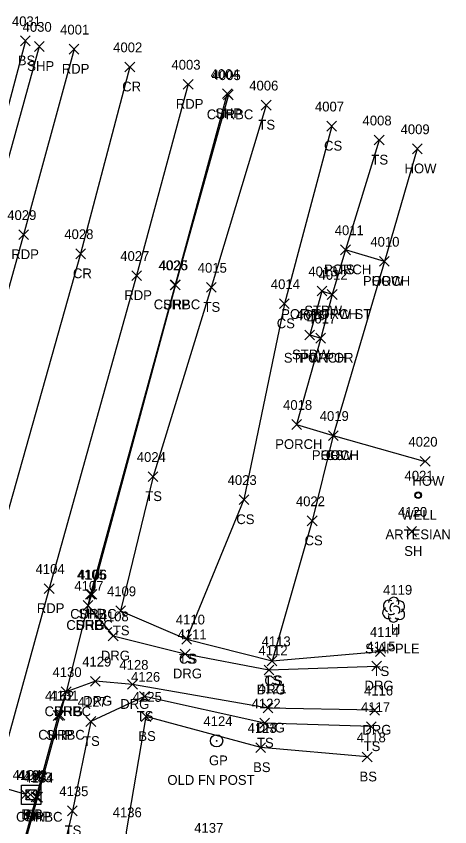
# Model space of a CAD drawing. Extents: x 1443912 to 1445411, y 621446 to 623693.
# Drawn here: x 1445024.9 to 1445113.5, y 623518.7 to 623684.4 of the extents above; entities that cross this region are included whole.
import ezdxf

# ---------------------------------------------------------------- set-up
doc = ezdxf.new("R2010")
doc.units = 0
for name, color, linetype in [('D_A', 7, 'Continuous'), ('D_I', 7, 'Continuous'), ('D_TIC', 7, 'Continuous'), ('DCP', 7, 'Continuous'), ('DS', 7, 'Continuous'), ('L_A', 7, 'Continuous'), ('L_C', 7, 'Continuous'), ('L_I', 7, 'Continuous'), ('L_TIC', 7, 'Continuous'), ('LBC', 7, 'Continuous'), ('LBF', 7, 'Continuous'), ('LELB', 7, 'Continuous'), ('LTD', 7, 'Continuous'), ('P_A', 7, 'Continuous'), ('P_I', 7, 'Continuous'), ('P_TIC', 7, 'Continuous'), ('PET', 7, 'Continuous'), ('PRC', 7, 'Continuous'), ('PSP', 7, 'Continuous'), ('R_A', 7, 'Continuous'), ('R_C', 7, 'Continuous'), ('R_I', 7, 'Continuous'), ('R_TIC', 7, 'Continuous'), ('RC', 7, 'Continuous'), ('RDG', 7, 'Continuous'), ('RGP', 7, 'Continuous'), ('U_A', 7, 'Continuous'), ('U_C', 7, 'Continuous'), ('U_I', 7, 'Continuous'), ('UWW', 7, 'Continuous')]:
    doc.layers.add(name, color=color, linetype=linetype)

msp = doc.modelspace()

# ---------------------------------------------------------------- linework, layer by layer
at = {"layer": 'D_TIC'}
for points in [[(1445025.82, 623524.34), (1445027.82, 623526.34)], [(1445027.82, 623524.34), (1445025.82, 623526.34)], [(1445026.79, 623524.3), (1445028.79, 623526.3)], [(1445028.79, 623524.3), (1445026.79, 623526.3)]]:
    msp.add_lwpolyline(points, dxfattribs=at)
at = {"layer": 'DCP'}
msp.add_lwpolyline([(1445026.82, 623525.34), (1444992.66, 623535.39)], dxfattribs=at)
at = {"layer": 'DS'}
for p, q in [((1445025.93, 623527.28), (1445029.93, 623527.28)), ((1445025.93, 623523.28), (1445025.93, 623527.28)), ((1445026.93, 623524.28), (1445026.93, 623526.28)), ((1445026.93, 623526.28), (1445028.93, 623526.28)), ((1445028.93, 623526.28), (1445028.93, 623524.28)), ((1445029.93, 623527.28), (1445029.93, 623523.28)), ((1445027.94, 623525.28), (1445027.94, 623525.28)), ((1445027.94, 623525.28), (1445027.94, 623525.28)), ((1445029.93, 623523.28), (1445025.93, 623523.28)), ((1445028.93, 623524.28), (1445026.93, 623524.28))]:
    msp.add_line(p, q, dxfattribs=at)
at = {"layer": 'L_TIC'}
for points in [[(1445025.76, 623678.41), (1445027.76, 623680.41)], [(1445027.76, 623678.41), (1445025.76, 623680.41)], [(1445075, 623665.26), (1445077, 623667.26)], [(1445077, 623665.26), (1445075, 623667.26)], [(1445088.39, 623660.97), (1445090.39, 623662.97)], [(1445090.39, 623660.97), (1445088.39, 623662.97)], [(1445098.11, 623658.12), (1445100.11, 623660.12)], [(1445100.11, 623658.12), (1445098.11, 623660.12)], [(1445105.9, 623656.33), (1445107.9, 623658.33)], [(1445107.9, 623656.33), (1445105.9, 623658.33)], [(1445091.21, 623635.68), (1445093.21, 623637.68)], [(1445093.21, 623635.68), (1445091.21, 623637.68)], [(1445091.21, 623635.68), (1445093.21, 623637.68)], [(1445093.21, 623635.68), (1445091.21, 623637.68)], [(1445099.16, 623633.33), (1445101.16, 623635.33)], [(1445101.16, 623633.33), (1445099.16, 623635.33)], [(1445099.16, 623633.33), (1445101.16, 623635.33)], [(1445101.16, 623633.33), (1445099.16, 623635.33)], [(1445063.77, 623628.01), (1445065.77, 623630.01)], [(1445065.77, 623628.01), (1445063.77, 623630.01)], [(1445086.39, 623627.27), (1445088.39, 623629.27)], [(1445088.39, 623627.27), (1445086.39, 623629.27)], [(1445088.48, 623626.56), (1445090.48, 623628.56)], [(1445090.48, 623626.56), (1445088.48, 623628.56)], [(1445088.48, 623626.56), (1445090.48, 623628.56)], [(1445090.48, 623626.56), (1445088.48, 623628.56)], [(1445078.72, 623624.66), (1445080.72, 623626.66)], [(1445080.72, 623624.66), (1445078.72, 623626.66)], [(1445083.89, 623618.29), (1445085.89, 623620.29)], [(1445085.89, 623618.29), (1445083.89, 623620.29)], [(1445086.15, 623617.62), (1445088.15, 623619.62)], [(1445088.15, 623617.62), (1445086.15, 623619.62)], [(1445086.15, 623617.62), (1445088.15, 623619.62)], [(1445088.15, 623617.62), (1445086.15, 623619.62)], [(1445081.22, 623599.97), (1445083.22, 623601.97)], [(1445083.22, 623599.97), (1445081.22, 623601.97)], [(1445088.72, 623597.71), (1445090.72, 623599.71)], [(1445090.72, 623597.71), (1445088.72, 623599.71)], [(1445088.72, 623597.71), (1445090.72, 623599.71)], [(1445090.72, 623597.71), (1445088.72, 623599.71)], [(1445088.72, 623597.71), (1445090.72, 623599.71)], [(1445090.72, 623597.71), (1445088.72, 623599.71)], [(1445107.52, 623592.45), (1445109.52, 623594.45)], [(1445109.52, 623592.45), (1445107.52, 623594.45)], [(1445051.86, 623589.33), (1445053.86, 623591.33)], [(1445053.86, 623589.33), (1445051.86, 623591.33)], [(1445070.45, 623584.62), (1445072.45, 623586.62)], [(1445072.45, 623584.62), (1445070.45, 623586.62)], [(1445084.41, 623580.28), (1445086.41, 623582.28)], [(1445086.41, 623580.28), (1445084.41, 623582.28)], [(1445104.74, 623578.12), (1445106.74, 623580.12)], [(1445106.74, 623578.12), (1445104.74, 623580.12)], [(1445045.22, 623561.88), (1445047.22, 623563.88)], [(1445047.22, 623561.88), (1445045.22, 623563.88)], [(1445058.73, 623556.1), (1445060.73, 623558.1)], [(1445060.73, 623556.1), (1445058.73, 623558.1)], [(1445058.73, 623556.1), (1445060.73, 623558.1)], [(1445060.73, 623556.1), (1445058.73, 623558.1)], [(1445098.34, 623553.56), (1445100.34, 623555.56)], [(1445100.34, 623553.56), (1445098.34, 623555.56)], [(1445076.19, 623551.66), (1445078.19, 623553.66)], [(1445078.19, 623551.66), (1445076.19, 623553.66)], [(1445076.19, 623551.66), (1445078.19, 623553.66)], [(1445078.19, 623551.66), (1445076.19, 623553.66)], [(1445050.11, 623544.39), (1445052.11, 623546.39)], [(1445052.11, 623544.39), (1445050.11, 623546.39)], [(1445039.13, 623539.27), (1445041.13, 623541.27)], [(1445041.13, 623539.27), (1445039.13, 623541.27)], [(1445050.41, 623540.29), (1445052.41, 623542.29)], [(1445052.41, 623540.29), (1445050.41, 623542.29)], [(1445074.7, 623538.93), (1445076.7, 623540.93)], [(1445076.7, 623538.93), (1445074.7, 623540.93)], [(1445096.52, 623538.22), (1445098.52, 623540.22)], [(1445098.52, 623538.22), (1445096.52, 623540.22)], [(1445073.88, 623533.93), (1445075.88, 623535.93)], [(1445075.88, 623533.93), (1445073.88, 623535.93)], [(1445095.64, 623532.02), (1445097.64, 623534.02)], [(1445097.64, 623532.02), (1445095.64, 623534.02)], [(1445035.37, 623521.01), (1445037.37, 623523.01)], [(1445037.37, 623521.01), (1445035.37, 623523.01)]]:
    msp.add_lwpolyline(points, dxfattribs=at)
at = {"layer": 'LBC'}
msp.add_lwpolyline([(1445106.9, 623657.33), (1445100.16, 623634.33), (1445089.72, 623598.71), (1445108.52, 623593.45)], dxfattribs=at)
at = {"layer": 'LBF'}
for points in [[(1445100.16, 623634.33), (1445092.21, 623636.68), (1445089.48, 623627.56), (1445087.15, 623618.62), (1445082.22, 623600.97), (1445089.72, 623598.71)], [(1445089.48, 623627.56), (1445087.39, 623628.27), (1445084.89, 623619.29), (1445087.15, 623618.62)]]:
    msp.add_lwpolyline(points, dxfattribs=at)
at = {"layer": 'LELB'}
for points in [[(1445026.76, 623679.41), (1445020.83, 623657.29)], [(1445076, 623666.26), (1445064.77, 623629.01), (1445052.86, 623590.33), (1445046.22, 623562.88), (1445059.73, 623557.1), (1445077.19, 623552.66), (1445099.34, 623554.56)], [(1445089.39, 623661.97), (1445079.72, 623625.66), (1445071.45, 623585.62), (1445059.73, 623557.1)], [(1445099.11, 623659.12), (1445092.21, 623636.68)], [(1445089.72, 623598.71), (1445085.41, 623581.28), (1445077.19, 623552.66)], [(1445097.52, 623539.22), (1445075.7, 623539.93), (1445051.11, 623545.39), (1445040.13, 623540.27), (1445036.37, 623522.01), (1445021.48, 623458.8), (1445005.96, 623403.97), (1444993.72, 623362.86), (1444977.79, 623311.56), (1444964.52, 623276.17), (1444977.62, 623272.11), (1444992.26, 623267.97), (1445018.74, 623260.17)], [(1445096.64, 623533.02), (1445074.88, 623534.93), (1445051.41, 623541.29), (1445047.34, 623517.69), (1445048.02, 623453.04), (1445034.58, 623396.92), (1445025.95, 623346.18)]]:
    msp.add_lwpolyline(points, dxfattribs=at)
at = {"layer": 'LTD'}
msp.add_line((1445102.04, 623563.18), (1445102.04, 623563.18), dxfattribs=at)
msp.add_line((1445102.04, 623563.18), (1445102.04, 623563.18), dxfattribs=at)
msp.add_arc((1445102.09, 623564.61), 1.05, 335.5272, 180.9563, dxfattribs=at)
for centre, major_axis, ratio, start_param, end_param in [((1445101.25, 623563.85), (1.21, -0.51), 0.895232, 1.570796, 4.712389), ((1445101.83, 623563.64), (-0.208, -0.792), 0.645439, 3.141593, 6.283185), ((1445103.08, 623563.76), (-1.14, -0.48), 0.949671, 1.570796, 4.712389), ((1445100.96, 623562.47), (0.58, -1.04), 0.959034, 3.141593, 6.283185), ((1445102.54, 623563.01), (-0.5, 0.667), 0.989748, 3.141593, 6.283185), ((1445103.04, 623562.35), (-1.09, 0.79), 0.841452, 1.570796, 4.712389), ((1445102.04, 623561.68), (0.26, 1.06), 0.942809, 1.570796, 4.712389), ((1445101.59, 623562.43), (-0.625, -0.083), 0.423636, 0, 3.141593)]:
    msp.add_ellipse(centre, major_axis=major_axis, ratio=ratio, start_param=start_param, end_param=end_param, dxfattribs=at)
at = {"layer": 'P_TIC'}
for points in [[(1445028.6, 623677.26), (1445030.6, 623679.26)], [(1445030.6, 623677.26), (1445028.6, 623679.26)], [(1445035.7, 623676.7), (1445037.7, 623678.7)], [(1445037.7, 623676.7), (1445035.7, 623678.7)], [(1445047.12, 623673.07), (1445049.12, 623675.07)], [(1445049.12, 623673.07), (1445047.12, 623675.07)], [(1445059.04, 623669.52), (1445061.04, 623671.52)], [(1445061.04, 623669.52), (1445059.04, 623671.52)], [(1445067.04, 623667.61), (1445069.04, 623669.61)], [(1445069.04, 623667.61), (1445067.04, 623669.61)], [(1445025.38, 623638.78), (1445027.38, 623640.78)], [(1445027.38, 623638.78), (1445025.38, 623640.78)], [(1445037.05, 623634.88), (1445039.05, 623636.88)], [(1445039.05, 623634.88), (1445037.05, 623636.88)], [(1445048.49, 623630.42), (1445050.49, 623632.42)], [(1445050.49, 623630.42), (1445048.49, 623632.42)], [(1445056.37, 623628.5), (1445058.37, 623630.5)], [(1445058.37, 623628.5), (1445056.37, 623630.5)], [(1445030.61, 623566.44), (1445032.61, 623568.44)], [(1445032.61, 623566.44), (1445030.61, 623568.44)], [(1445039.05, 623565.3), (1445041.05, 623567.3)], [(1445041.05, 623565.3), (1445039.05, 623567.3)], [(1445038.54, 623562.99), (1445040.54, 623564.99)], [(1445040.54, 623562.99), (1445038.54, 623564.99)], [(1445034.08, 623545.36), (1445036.08, 623547.36)], [(1445036.08, 623545.36), (1445034.08, 623547.36)], [(1445032.45, 623540.5), (1445034.45, 623542.5)], [(1445034.45, 623540.5), (1445032.45, 623542.5)], [(1445027.92, 623523.87), (1445029.92, 623525.87)], [(1445029.92, 623523.87), (1445027.92, 623525.87)]]:
    msp.add_lwpolyline(points, dxfattribs=at)
at = {"layer": 'PET'}
for points in [[(1445036.7, 623677.7), (1445026.38, 623639.78), (1445008.65, 623576.15), (1444996.95, 623532.89), (1444979.78, 623472.47), (1444964.83, 623416.22), (1444955.71, 623382.54), (1444949.17, 623358.13), (1444939.29, 623323.43), (1444926.27, 623275.91), (1444914.83, 623235.04), (1444901.53, 623186.46), (1444892.14, 623152.69), (1444883.14, 623119.13), (1444870.13, 623073.23), (1444861.49, 623043.31), (1444850.84, 623006.82), (1444834.61, 622954.83), (1444817.28, 622898.33)], [(1445060.04, 623670.52), (1445049.49, 623631.42), (1445031.61, 623567.44), (1445020.44, 623527.05), (1445003.5, 623465.59), (1444988.1, 623409.14), (1444976.63, 623367.03), (1444962.49, 623315.05), (1444949.49, 623267.35), (1444937.78, 623225.39), (1444926.09, 623182.22), (1444915.48, 623145.05), (1444906.98, 623113.48), (1444893.64, 623066.1), (1444886.06, 623037.31), (1444876.58, 623001.08), (1444863.33, 622947.05), (1444849.43, 622890.74)]]:
    msp.add_lwpolyline(points, dxfattribs=at)
at = {"layer": 'PRC'}
msp.add_lwpolyline([(1445048.12, 623674.07), (1445038.05, 623635.88), (1445020.14, 623572.7), (1445008.5, 623529.11), (1444991.68, 623469.75), (1444976.21, 623412.44), (1444964.87, 623369.69), (1444950.64, 623318.47), (1444938.05, 623272.58), (1444925.39, 623227.3), (1444913.85, 623184.57), (1444903.74, 623148.67), (1444894.97, 623116.18), (1444881.8, 623068.92), (1444873.97, 623040.25), (1444864.1, 623005.34), (1444846.73, 622950.74), (1444829.37, 622896.11)], dxfattribs=at)
at = {"layer": 'PSP'}
for points in [[(1445029.6, 623678.26), (1445021.68, 623649.55), (1445019.78, 623642.34), (1445019.32, 623640.93), (1445017.21, 623633.02), (1445017.08, 623631.73), (1445013.01, 623618.17), (1445011.68, 623612.99), (1445004.58, 623587.1), (1444990.43, 623535.38), (1444989.65, 623532.72), (1444983.26, 623509.22), (1444982.17, 623505.29), (1444973.63, 623474.39), (1444957.7, 623416.57), (1444946.06, 623374.16), (1444939.52, 623351.37), (1444938.45, 623347.36), (1444929.03, 623313.43)], [(1445068.04, 623668.61), (1445057.37, 623629.5), (1445040.05, 623566.3), (1445039.54, 623563.99), (1445035.08, 623546.36), (1445033.45, 623541.5), (1445028.92, 623524.87), (1445011.88, 623462.96), (1444996.28, 623406.54), (1444984.52, 623364.95), (1444970.17, 623313)]]:
    msp.add_lwpolyline(points, dxfattribs=at)
at = {"layer": 'R_TIC'}
for points in [[(1445067.26, 623667.38), (1445069.26, 623669.38)], [(1445069.26, 623667.38), (1445067.26, 623669.38)], [(1445056.42, 623628.53), (1445058.42, 623630.53)], [(1445058.42, 623628.53), (1445056.42, 623630.53)], [(1445039.33, 623565.27), (1445041.33, 623567.27)], [(1445041.33, 623565.27), (1445039.33, 623567.27)], [(1445038.54, 623562.99), (1445040.54, 623564.99)], [(1445040.54, 623562.99), (1445038.54, 623564.99)], [(1445038.54, 623562.99), (1445040.54, 623564.99)], [(1445040.54, 623562.99), (1445038.54, 623564.99)], [(1445043.7, 623556.75), (1445045.7, 623558.75)], [(1445045.7, 623556.75), (1445043.7, 623558.75)], [(1445058.43, 623553.08), (1445060.43, 623555.08)], [(1445060.43, 623553.08), (1445058.43, 623555.08)], [(1445075.56, 623549.8), (1445077.56, 623551.8)], [(1445077.56, 623549.8), (1445075.56, 623551.8)], [(1445097.61, 623550.61), (1445099.61, 623552.61)], [(1445099.61, 623550.61), (1445097.61, 623552.61)], [(1445040.07, 623547.5), (1445042.07, 623549.5)], [(1445042.07, 623547.5), (1445040.07, 623549.5)], [(1445047.66, 623546.85), (1445049.66, 623548.85)], [(1445049.66, 623546.85), (1445047.66, 623548.85)], [(1445034.08, 623545.36), (1445036.08, 623547.36)], [(1445036.08, 623545.36), (1445034.08, 623547.36)], [(1445034.08, 623545.36), (1445036.08, 623547.36)], [(1445036.08, 623545.36), (1445034.08, 623547.36)], [(1445075.38, 623542.02), (1445077.38, 623544.02)], [(1445077.38, 623542.02), (1445075.38, 623544.02)], [(1445097.18, 623541.58), (1445099.18, 623543.58)], [(1445099.18, 623541.58), (1445097.18, 623543.58)], [(1445032.8, 623540.56), (1445034.8, 623542.56)], [(1445034.8, 623540.56), (1445032.8, 623542.56)], [(1445028.25, 623523.79), (1445030.25, 623525.79)], [(1445030.25, 623523.79), (1445028.25, 623525.79)]]:
    msp.add_lwpolyline(points, dxfattribs=at)
at = {"layer": 'RC'}
for points in [[(1445068.26, 623668.38), (1445057.42, 623629.53), (1445040.33, 623566.27), (1445039.54, 623563.99)], [(1445035.08, 623546.36), (1445033.8, 623541.56), (1445029.25, 623524.79), (1445012.06, 623463.08), (1444996.39, 623406.47), (1444984.8, 623364.92), (1444970.42, 623313.05), (1444960.98, 623279.58), (1444959.91, 623275.87)]]:
    msp.add_lwpolyline(points, dxfattribs=at)
at = {"layer": 'RDG'}
for points in [[(1445039.54, 623563.99), (1445044.7, 623557.75), (1445059.43, 623554.08), (1445076.56, 623550.8), (1445098.61, 623551.61)], [(1445098.18, 623542.58), (1445076.38, 623543.02), (1445048.66, 623547.85), (1445041.07, 623548.5), (1445035.08, 623546.36)]]:
    msp.add_lwpolyline(points, dxfattribs=at)
at = {"layer": 'RGP'}
msp.add_line((1445065.86, 623536.32), (1445065.86, 623536.32), dxfattribs=at)
for radius in [1.25, 0.0833]:
    msp.add_circle((1445065.86, 623536.32), radius, dxfattribs=at)
at = {"layer": 'UWW'}
for radius in [0.667, 0.625, 0.583, 0.542]:
    msp.add_circle((1445107.06, 623586.52), radius, dxfattribs=at)

# ---------------------------------------------------------------- texts
at = {"layer": 'D_A'}
for s, p in [('DIB', (1445025.89, 623520.3)), ('P', (1445026.2, 623520.34)), ('DI', (1445026.99, 623520.28))]:
    msp.add_text(s, height=2, dxfattribs=at).set_placement(p)
at = {"layer": 'D_I'}
for s, p in [('4194', (1445024.13, 623528.34)), ('4193', (1445025.1, 623528.3)), ('4192', (1445025.25, 623528.28))]:
    msp.add_text(s, height=2, dxfattribs=at).set_placement(p)
at = {"layer": 'L_A'}
for s, p in [('BS', (1445025.2, 623674.41)), ('TS', (1445074.41, 623661.26)), ('CS', (1445087.83, 623656.97)), ('TS', (1445097.52, 623654.12)), ('HOW', (1445104.29, 623652.33)), ('PORCH', (1445087.83, 623631.68)), ('TS', (1445090.62, 623631.68)), ('PORCH', (1445095.78, 623629.33)), ('HOW', (1445097.55, 623629.33)), ('TS', (1445063.18, 623624.01)), ('POR STPW ST', (1445079.06, 623622.56)), ('STPW', (1445083.79, 623623.27)), ('PORCH', (1445085.1, 623622.56)), ('CS', (1445078.16, 623620.66)), ('STPW POR', (1445079.6, 623613.62)), ('STPW', (1445081.29, 623614.29)), ('PORCH', (1445082.77, 623613.62)), ('PORCH', (1445077.84, 623595.97)), ('PORCH', (1445085.34, 623593.71)), ('HOW', (1445087.11, 623593.71)), ('CS', (1445088.16, 623593.71)), ('HOW', (1445105.9, 623588.45)), ('TS', (1445051.27, 623585.33)), ('CS', (1445069.89, 623580.62)), ('CS', (1445083.85, 623576.28)), ('SH', (1445104.23, 623574.12)), ('TS', (1445044.63, 623557.88)), ('H', (1445101.48, 623558.18)), ('TS', (1445058.14, 623552.1)), ('CS', (1445058.17, 623552.1)), ('TS', (1445097.75, 623549.56)), ('TS', (1445075.6, 623547.66)), ('CS', (1445075.63, 623547.66)), ('TS', (1445049.52, 623540.39)), ('BS', (1445049.85, 623536.29)), ('TS', (1445038.54, 623535.27)), ('TS', (1445074.11, 623534.93)), ('TS', (1445095.93, 623534.22)), ('BS', (1445073.32, 623529.93)), ('BS', (1445095.08, 623528.02)), ('TS', (1445034.78, 623517.01))]:
    msp.add_text(s, height=2, dxfattribs=at).set_placement(p)
at = {"layer": 'L_C'}
msp.add_text('S.APPLE', height=2, dxfattribs=at).set_placement((1445096.23, 623554.18))
at = {"layer": 'L_I'}
for s, p in [('4031', (1445023.99, 623682.41)), ('4006', (1445072.53, 623669.26)), ('4007', (1445085.97, 623664.97)), ('4008', (1445095.7, 623662.12)), ('4009', (1445103.48, 623660.33)), ('4011', (1445090.01, 623639.68)), ('4011', (1445090.01, 623639.68)), ('4010', (1445097.3, 623637.33)), ('4010', (1445097.3, 623637.33)), ('4015', (1445062, 623632.01)), ('4013', (1445084.62, 623631.27)), ('4012', (1445086.71, 623630.56)), ('4012', (1445086.71, 623630.56)), ('4014', (1445076.95, 623628.66)), ('4016', (1445082.07, 623622.29)), ('4017', (1445084.38, 623621.62)), ('4017', (1445084.38, 623621.62)), ('4018', (1445079.45, 623603.97)), ('4019', (1445086.94, 623601.71)), ('4019', (1445086.94, 623601.71)), ('4019', (1445086.94, 623601.71)), ('4020', (1445105.09, 623596.45)), ('4024', (1445049.53, 623593.33)), ('4023', (1445068.11, 623588.62)), ('4022', (1445082.07, 623584.28)), ('4120', (1445102.96, 623582.12)), ('4109', (1445043.44, 623565.88)), ('4119', (1445099.91, 623566.18)), ('4110', (1445057.52, 623560.1)), ('4110', (1445057.52, 623560.1)), ('4114', (1445097.21, 623557.56)), ('4113', (1445075.06, 623555.66)), ('4113', (1445075.06, 623555.66)), ('4126', (1445048.36, 623548.39)), ('4125', (1445048.71, 623544.29)), ('4127', (1445037.44, 623543.27)), ('4122', (1445073.01, 623542.93)), ('4117', (1445095.39, 623542.22)), ('4123', (1445072.19, 623537.93)), ('4118', (1445094.51, 623536.02)), ('4135', (1445033.68, 623525.01)), ('4136', (1445044.6, 623520.69)), ('4137', (1445061.28, 623517.52))]:
    msp.add_text(s, height=2, dxfattribs=at).set_placement(p)
at = {"layer": 'P_A'}
for s, p in [('SHP', (1445027.14, 623673.26)), ('RDP', (1445034.19, 623672.7)), ('CR', (1445046.55, 623669.07)), ('RDP', (1445057.52, 623665.52)), ('SHP', (1445065.57, 623663.61)), ('RDP', (1445023.87, 623634.78)), ('CR', (1445036.48, 623630.88)), ('RDP', (1445046.98, 623626.42)), ('SHP', (1445054.9, 623624.5)), ('RDP', (1445029.09, 623562.44)), ('SHP', (1445037.58, 623561.3)), ('SHP', (1445037.07, 623558.99)), ('SHP', (1445032.62, 623541.36)), ('SHP', (1445030.99, 623536.5)), ('SHP', (1445026.46, 623519.87))]:
    msp.add_text(s, height=2, dxfattribs=at).set_placement(p)
at = {"layer": 'P_I'}
for s, p in [('4030', (1445026.18, 623681.26)), ('4001', (1445033.85, 623680.7)), ('4002', (1445044.7, 623677.07)), ('4003', (1445056.62, 623673.52)), ('4004', (1445064.62, 623671.61)), ('4029', (1445023.04, 623642.78)), ('4028', (1445034.71, 623638.88)), ('4027', (1445046.15, 623634.42)), ('4026', (1445053.97, 623632.5)), ('4104', (1445028.83, 623570.44)), ('4105', (1445037.28, 623569.3)), ('4107', (1445036.77, 623566.99)), ('4130', (1445032.3, 623549.36)), ('4132', (1445030.76, 623544.5)), ('4133', (1445026.23, 623527.87))]:
    msp.add_text(s, height=2, dxfattribs=at).set_placement(p)
at = {"layer": 'R_A'}
for s, p in [('CURBC', (1445063.85, 623663.38)), ('CURBC', (1445053, 623624.53)), ('CURBC', (1445035.91, 623561.27)), ('CURBC', (1445035.12, 623558.99)), ('DRG', (1445037.03, 623558.99)), ('DRG', (1445042.19, 623552.75)), ('DRG', (1445056.92, 623549.08)), ('DRG', (1445074.05, 623545.8)), ('DRG', (1445096.1, 623546.61)), ('DRG', (1445038.56, 623543.5)), ('DRG', (1445046.15, 623542.85)), ('CURBC', (1445030.67, 623541.36)), ('DRG', (1445032.57, 623541.36)), ('DRG', (1445073.87, 623538.02)), ('DRG', (1445095.67, 623537.58)), ('CURBC', (1445029.38, 623536.56)), ('GP', (1445064.29, 623531.32)), ('CURBC', (1445024.83, 623519.79))]:
    msp.add_text(s, height=2, dxfattribs=at).set_placement(p)
at = {"layer": 'R_C'}
msp.add_text('OLD FN POST', height=2, dxfattribs=at).set_placement((1445055.79, 623527.32))
at = {"layer": 'R_I'}
for s, p in [('4005', (1445064.85, 623671.38)), ('4025', (1445054.08, 623632.53)), ('4106', (1445037.5, 623569.27)), ('4107', (1445036.77, 623566.99)), ('4107', (1445036.77, 623566.99)), ('4108', (1445041.93, 623560.75)), ('4111', (1445057.87, 623557.08)), ('4115', (1445096.49, 623554.61)), ('4112', (1445074.43, 623553.8)), ('4129', (1445038.37, 623551.5)), ('4128', (1445045.97, 623550.85)), ('4130', (1445032.3, 623549.36)), ('4130', (1445032.3, 623549.36)), ('4121', (1445074.25, 623546.02)), ('4131', (1445031.67, 623544.56)), ('4116', (1445096, 623545.58)), ('4124', (1445063.16, 623539.32)), ('4134', (1445026.56, 623527.79))]:
    msp.add_text(s, height=2, dxfattribs=at).set_placement(p)
at = {"layer": 'U_A'}
msp.add_text('WELL', height=2, dxfattribs=at).set_placement((1445103.63, 623581.52))
at = {"layer": 'U_C'}
msp.add_text('ARTESIAN', height=2, dxfattribs=at).set_placement((1445100.39, 623577.52))
at = {"layer": 'U_I'}
msp.add_text('4021', height=2, dxfattribs=at).set_placement((1445104.29, 623589.52))

doc.saveas('drawing.dxf')
